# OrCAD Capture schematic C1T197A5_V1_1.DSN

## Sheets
1 002_Block digram: title: Telink-Semi; rev: V1.1; note: C1T197A5
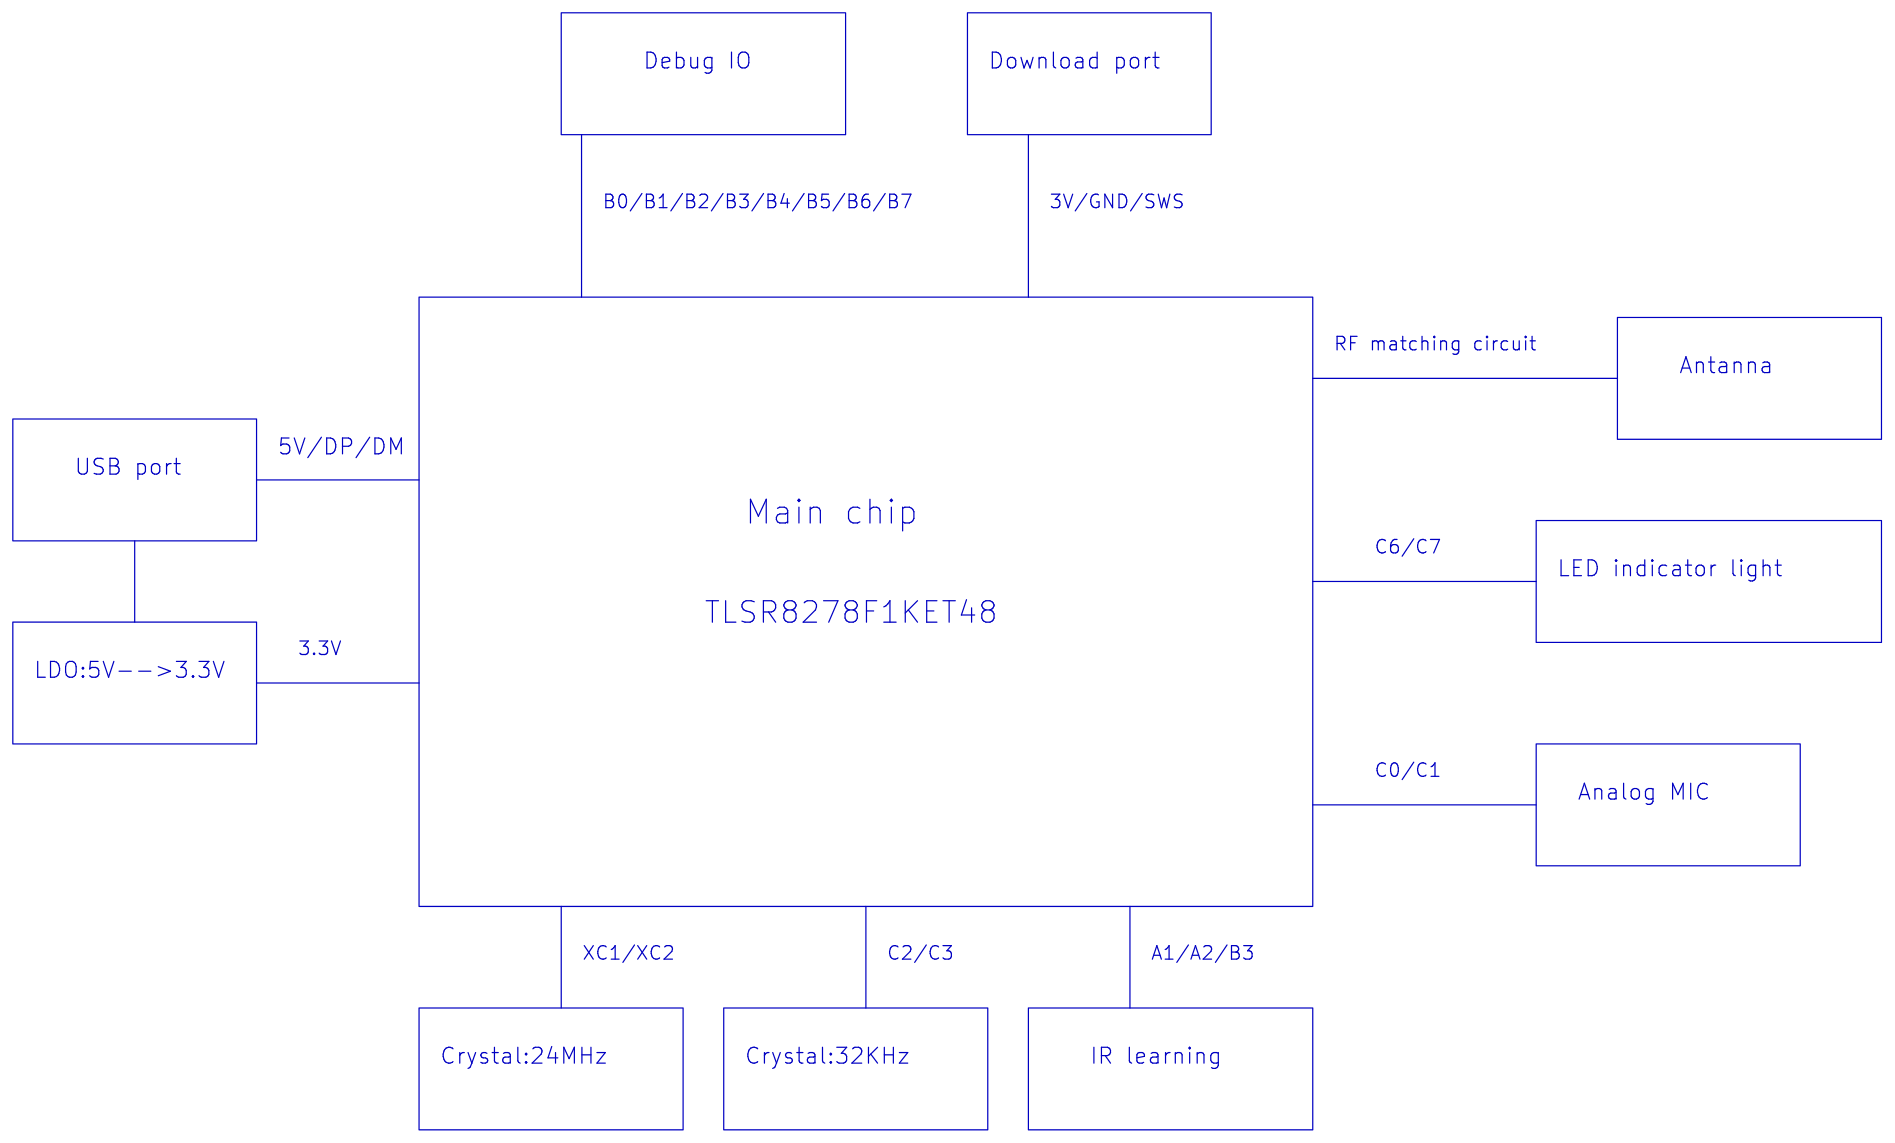
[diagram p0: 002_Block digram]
2 001_Log
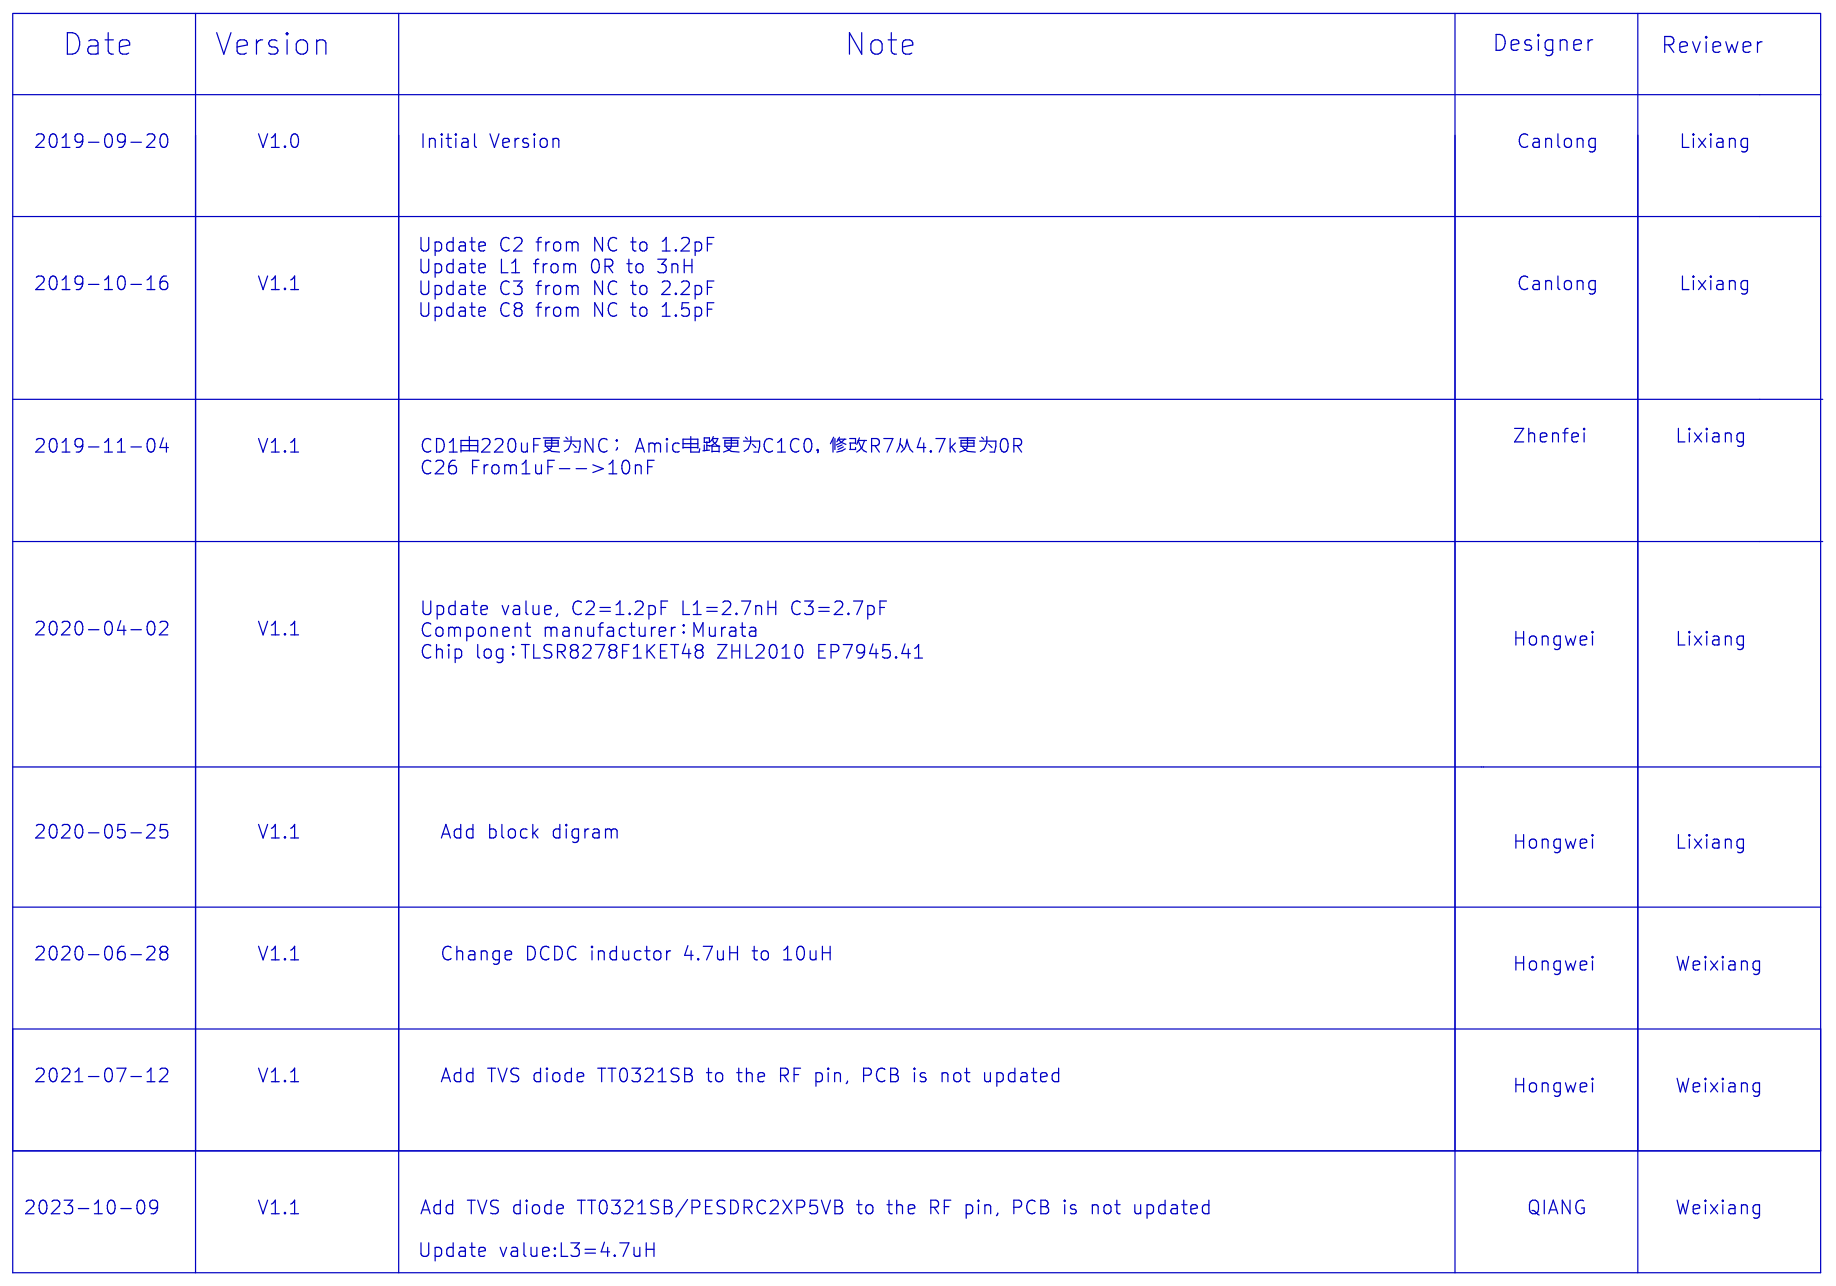
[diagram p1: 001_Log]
3 003_CPU: size A4
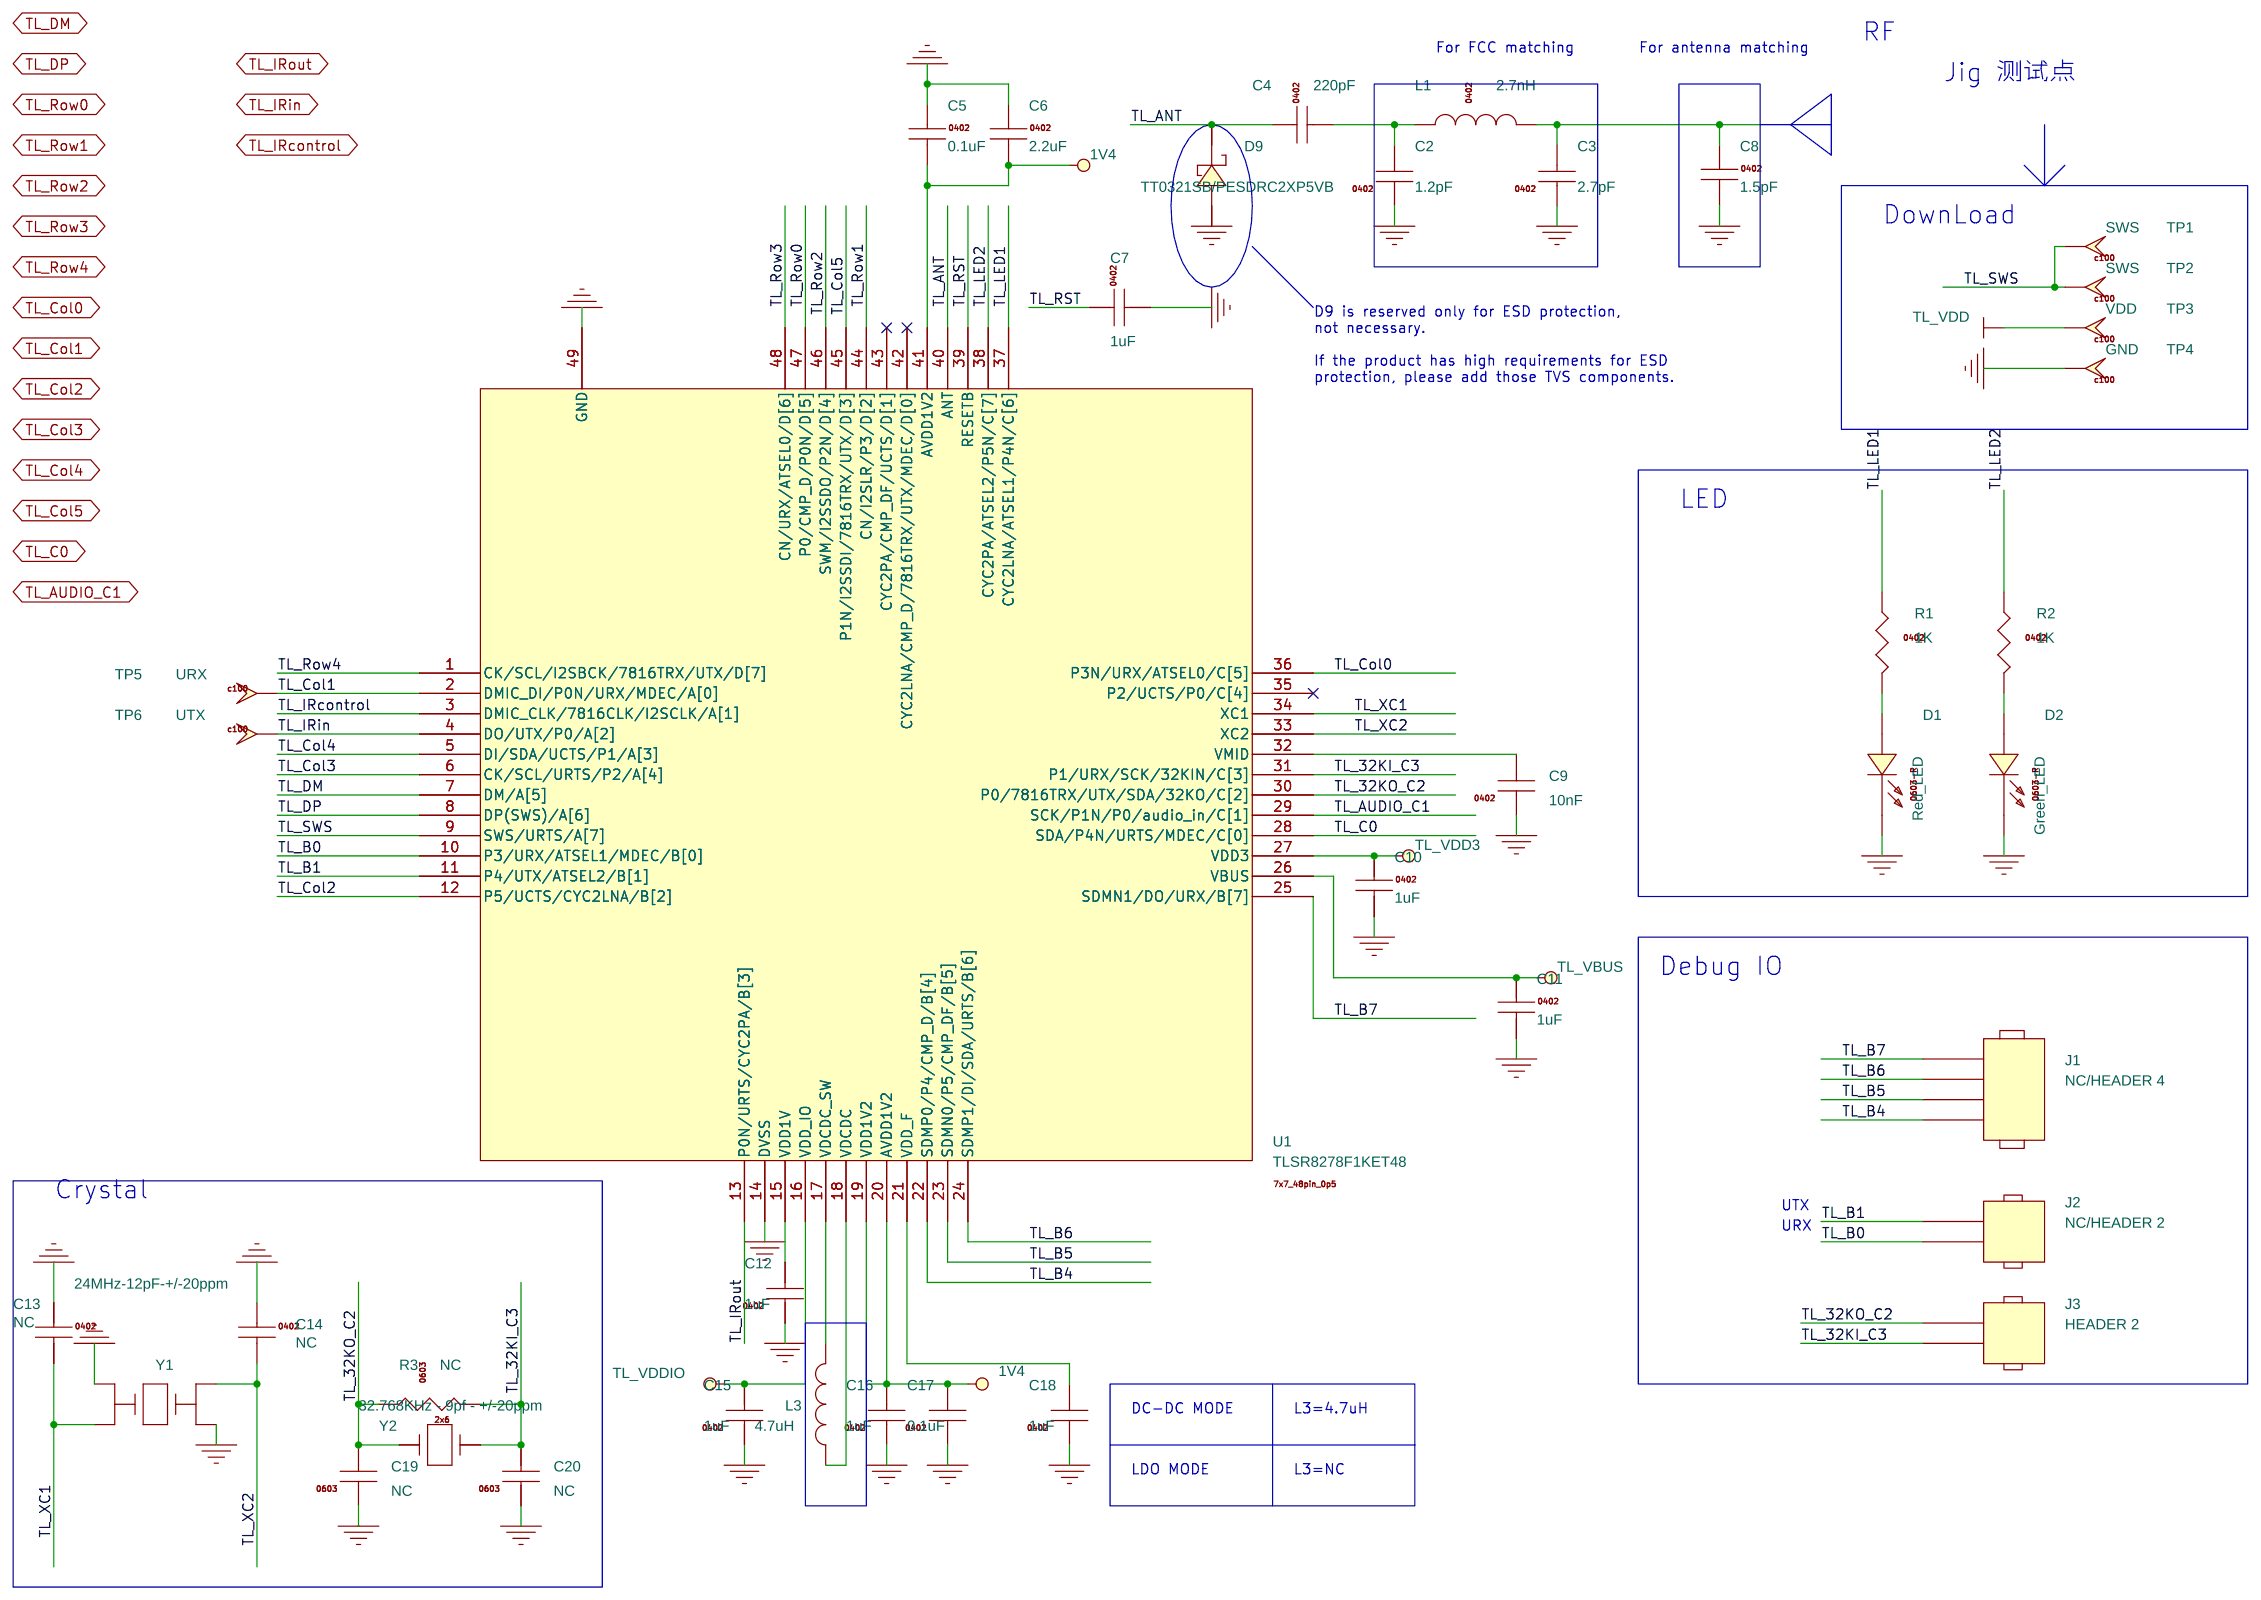
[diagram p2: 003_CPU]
4 004_Key: size A4
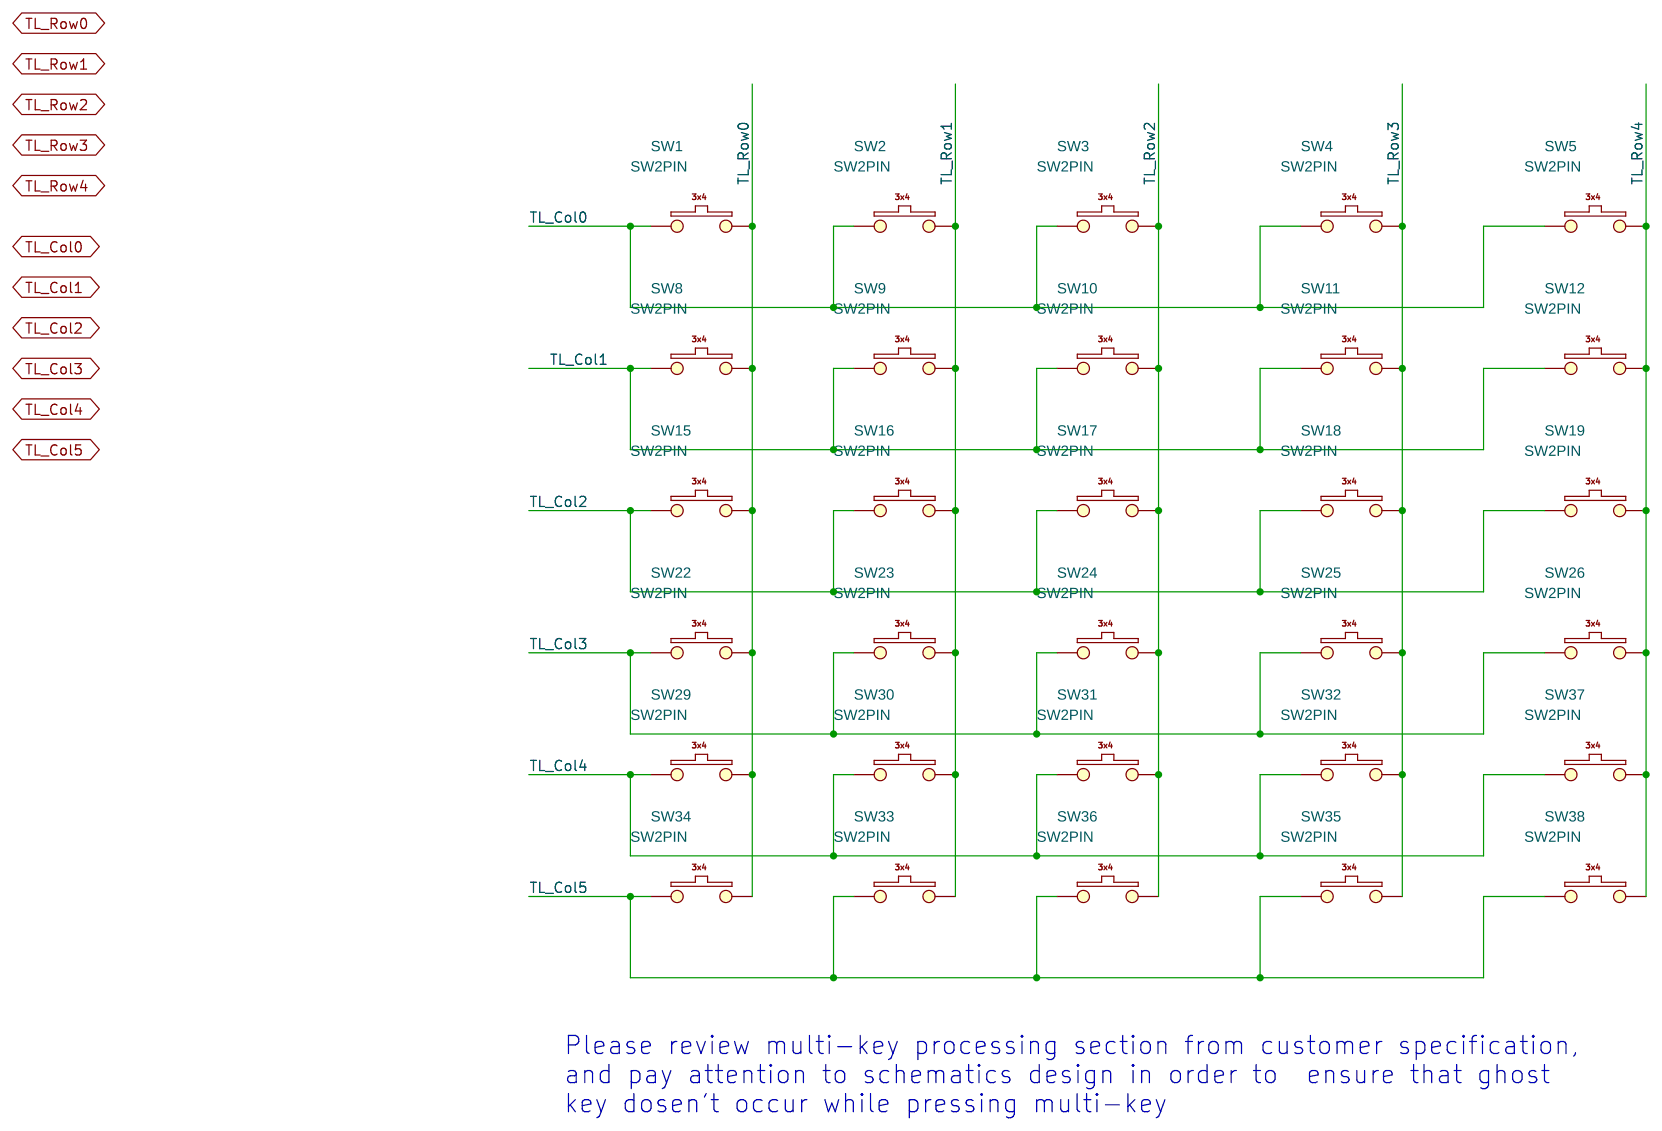
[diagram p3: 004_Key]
5 005_Power: size A4
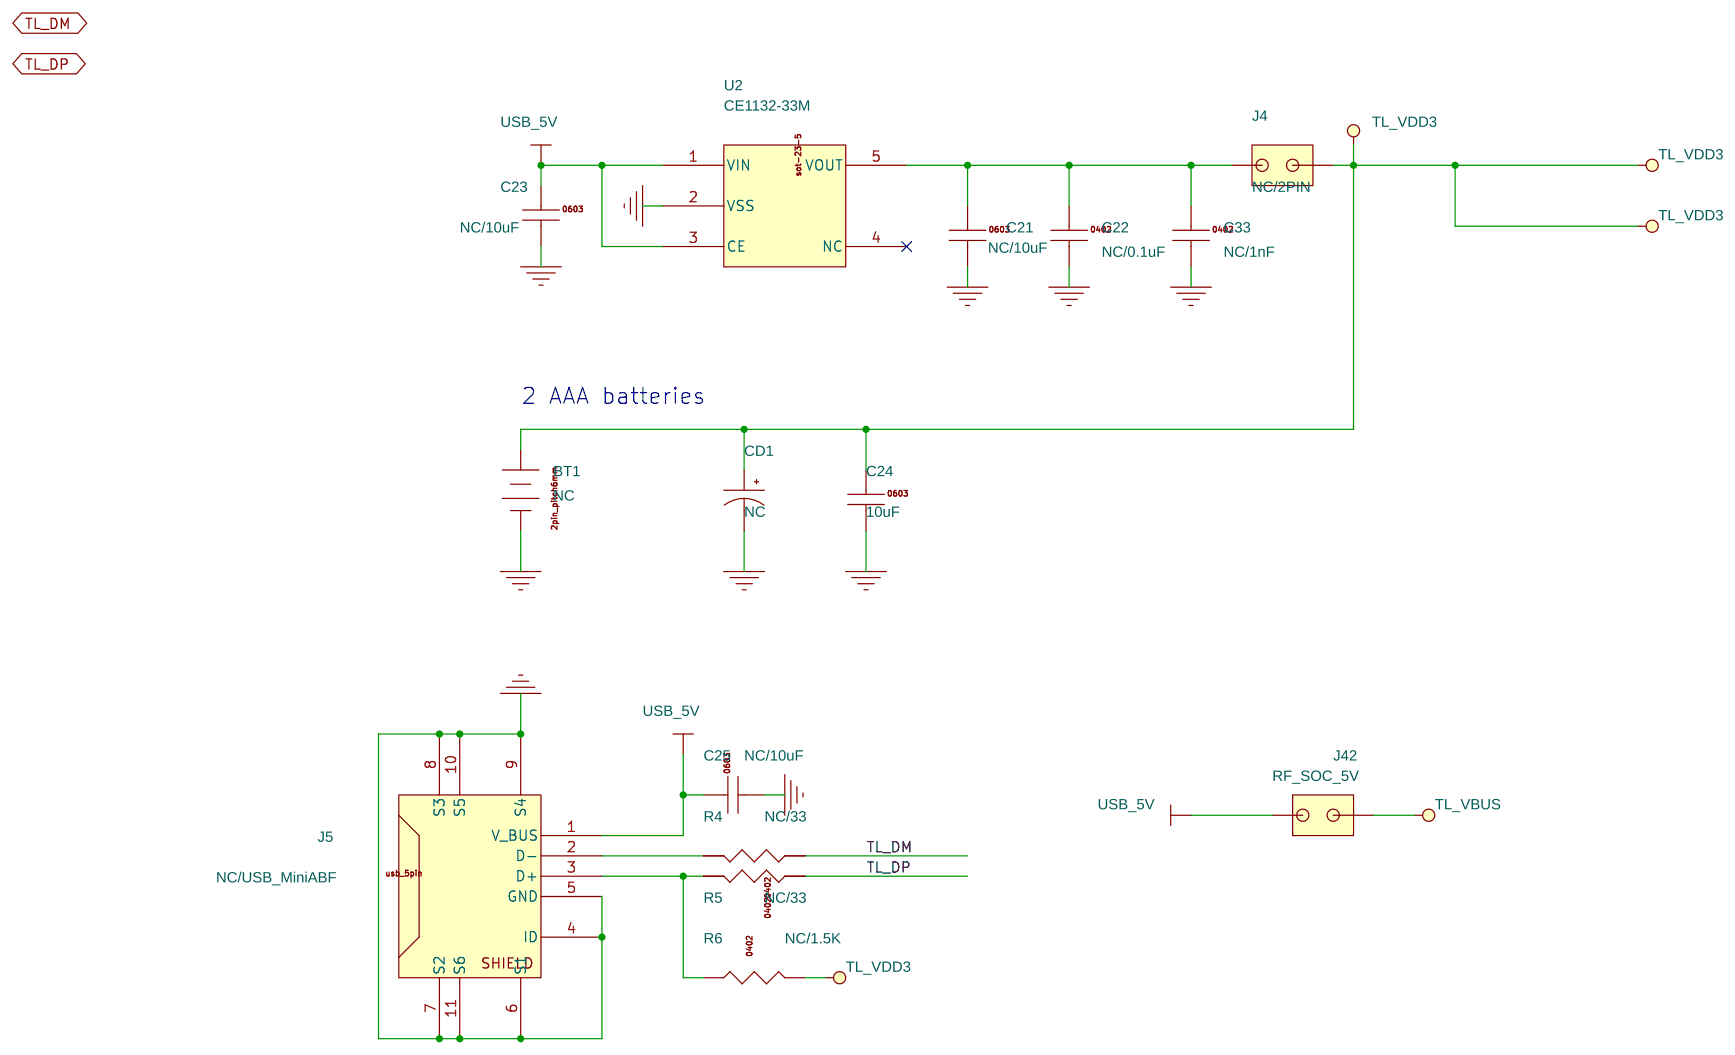
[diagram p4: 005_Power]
6 006_Audio: size A4
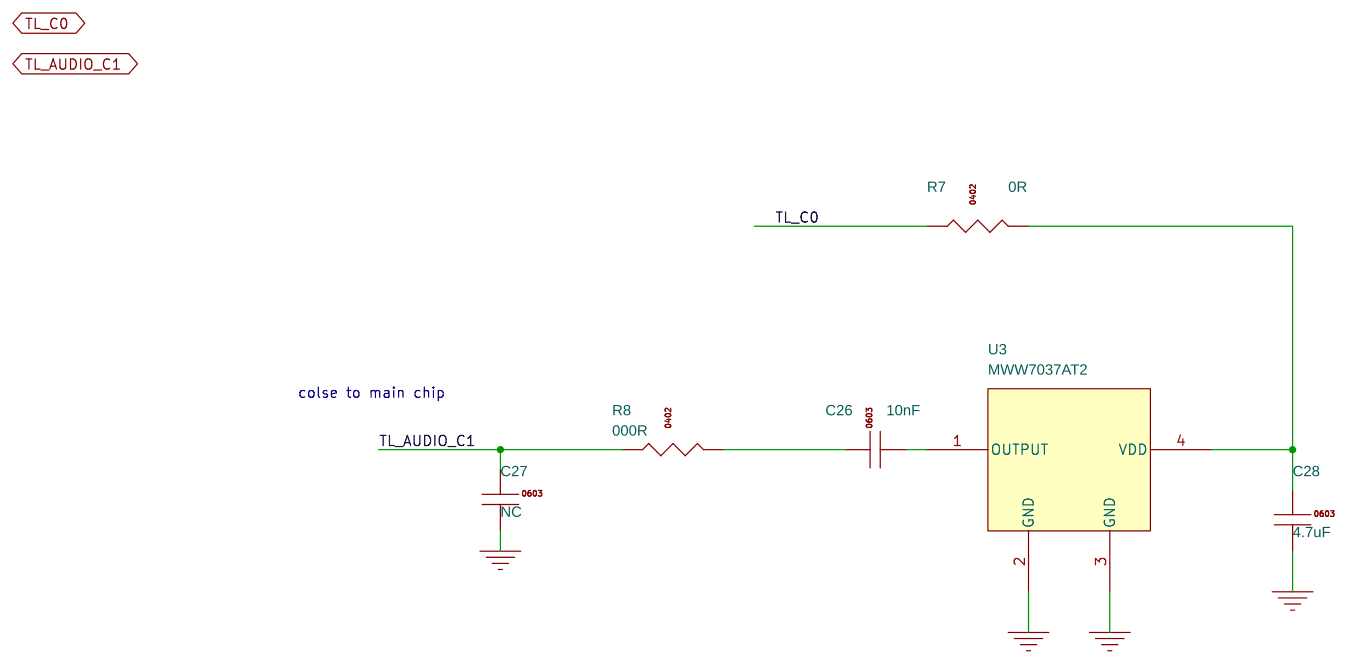
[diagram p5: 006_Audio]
7 007_IR: size A4
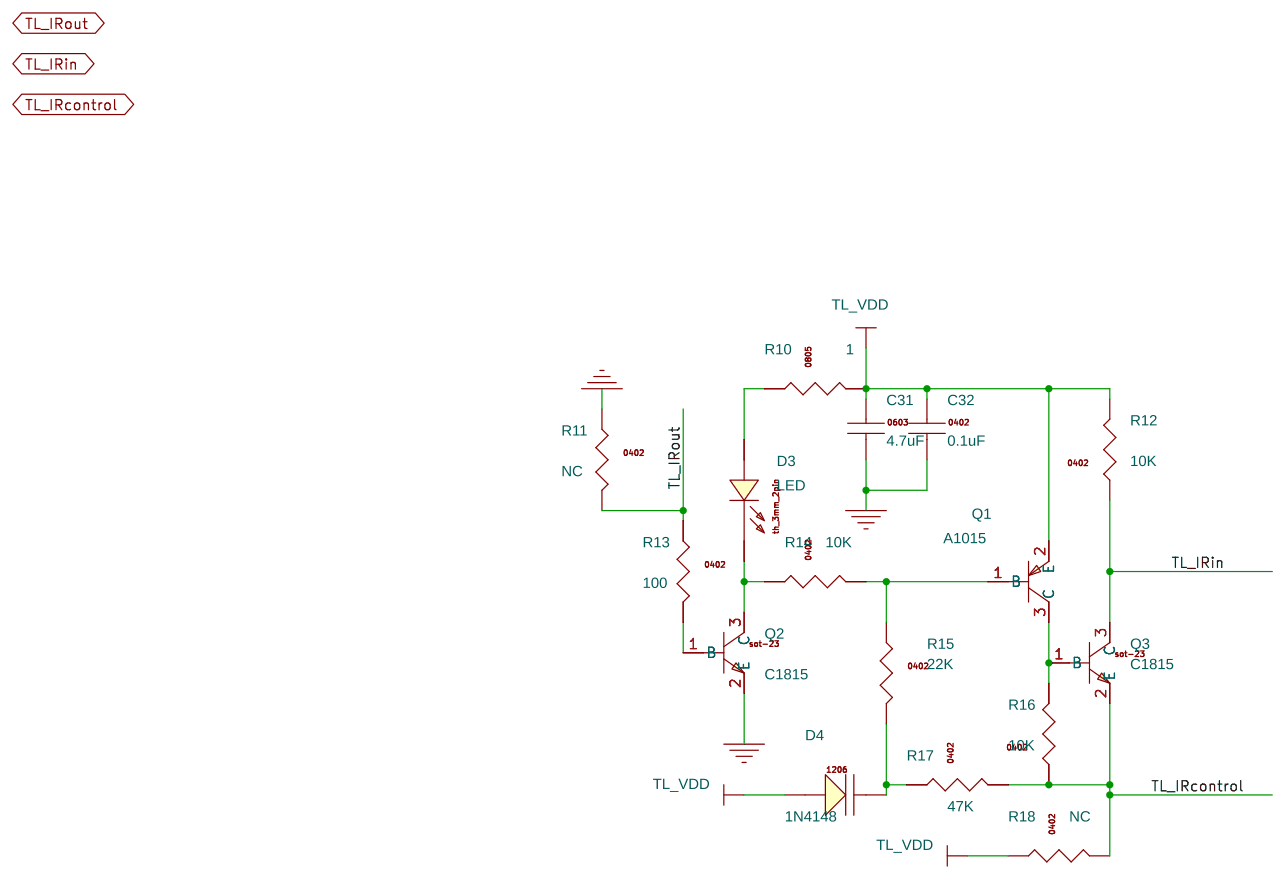
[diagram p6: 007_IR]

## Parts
sheet 003_CPU
C2  1.2pF  [0402]
C3  2.7pF  [0402]
C4  220pF  [0402]
C5  0.1uF  [0402]
C6  2.2uF  [0402]
C7  1uF  [0402]
C8  1.5pF  [0402]
C9  10nF  [0402]
C10  1uF  [0402]
C11  1uF  [0402]
C12  1uF  [0402]
C13  NC  [0402]
C14  NC  [0402]
C15  1uF  [0402]
C16  1uF  [0402]
C17  0.1uF  [0402]
C18  1uF  [0402]
C19  NC  [0402]
C20  NC  [0402]
D1  Red_LED  [0603-LED]
D2  Green_LED  [0603-LED]
D9  TT0321SB/PESDRC2XP5VB  [SOD-123]
J1  NC/HEADER 4  [hdr254f-1x4x850]
J2  NC/HEADER 2  [hdr254f-1x2x850]
J3  HEADER 2  [hdr254f-1x2x850]
L1  2.7nH  [0402]
L3  4.7uH  [0805L]
R1  1K  [0402]
R2  1K  [0402]
R3  NC  [0402]
TP1  SWS  [tp100]
TP2  SWS  [tp100]
TP3  VDD  [tp100]
TP4  GND  [tp100]
TP5  URX  [tp100]
TP6  UTX  [tp100]
U1  TLSR8278F1KET48  [qfn_7x7_48pin_0p5_4p20x4p20]
Y1  24MHz-12pF-+/-20ppm  [OSCCC250X320X110]
Y2  32.768KHz - 9pf - +/-20ppm  [OSC_2x6]
sheet 004_Key
SW1  SW2PIN  [sw_out6_in3]
SW2  SW2PIN  [sw_out6_in3]
SW3  SW2PIN  [sw_out6_in3]
SW4  SW2PIN  [sw_out6_in3]
SW5  SW2PIN  [sw_out6_in3]
SW8  SW2PIN  [sw_out6_in3]
SW9  SW2PIN  [sw_out6_in3]
SW10  SW2PIN  [sw_out6_in3]
SW11  SW2PIN  [sw_out6_in3]
SW12  SW2PIN  [sw_out6_in3]
SW15  SW2PIN  [sw_out6_in3]
SW16  SW2PIN  [sw_out6_in3]
SW17  SW2PIN  [sw_out6_in3]
SW18  SW2PIN  [sw_out6_in3]
SW19  SW2PIN  [sw_out6_in3]
SW22  SW2PIN  [sw_out6_in3]
SW23  SW2PIN  [sw_out6_in3]
SW24  SW2PIN  [sw_out6_in3]
SW25  SW2PIN  [sw_out6_in3]
SW26  SW2PIN  [sw_out6_in3]
SW29  SW2PIN  [sw_out6_in3]
SW30  SW2PIN  [sw_out6_in3]
SW31  SW2PIN  [sw_out6_in3]
SW32  SW2PIN  [sw_out6_in3]
SW33  SW2PIN  [sw_out6_in3]
SW34  SW2PIN  [sw_out6_in3]
SW35  SW2PIN  [sw_out6_in3]
SW36  SW2PIN  [sw_out6_in3]
SW37  SW2PIN  [sw_out6_in3]
SW38  SW2PIN  [sw_out6_in3]
sheet 005_Power
BT1  NC  [bat_2dip]
C21  NC/10uF  [0603c]
C22  NC/0.1uF  [0402]
C23  NC/10uF  [0603c]
C24  10uF  [0603c]
C25  NC/10uF  [0603c]
C33  NC/1nF  [0402]
CD1  NC  [cd2p0_4p0b]
J4  NC/2PIN  [HDR254F-1X2X850]
J5  NC/USB_MiniABF  [microusb_dip]
J42  RF_SOC_5V  [HDR254F-1X2X850]
R4  NC/33  [0402]
R5  NC/33  [0402]
R6  NC/1.5K  [0402]
U2  CE1132-33M  [sot-23-5]
sheet 006_Audio
C26  10nF  [0402]
C27  NC  [0402]
C28  4.7uF  [0402]
R7  0R  [0402]
R8  000R  [0402]
U3  MWW7037AT2  [ga_bfa423_a83]
sheet 007_IR
C31  4.7uF  [0402]
C32  0.1uF  [0402]
D3  LED  [led_th_2p54mm_2pin]
D4  1N4148  [SOD80]
Q1  A1015  [SOT-23]
Q2  C1815  [SOT-23]
Q3  C1815  [SOT-23]
R10  1  [0402]
R11  NC  [0402]
R12  10K  [0402]
R13  100  [0402]
R14  10K  [0402]
R15  22K  [0402]
R16  10K  [0402]
R17  47K  [0402]
R18  NC  [0402]

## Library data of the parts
C2-C4 C8 = C1608_NC_0
C5-C7 C9-C11 C22 C32 C33 = C1005X5R1C104K
C12 C15-C18 = C1005X5R1C105K
C13 C14 = C1005_NC
C19 C20 = C1608_NC
D1 D2 = 0603D_Red
D9 = DIODE_SCHOTTKY_0
J1 = HEADER_4
J2 J3 = HEADER_2
L1 = MLK1608_0
L3 = IND_0
R1 R2 R6-R8 = RS0402K472JT
R3 = RS0603K102JT
TP1-TP6 = TestPad100
U1 = TLSR8278F1KET48_2
Y1 = CRYSTAL4_SM_0
Y2 = OSC_2x6_2pin_16Mhz
SW1-SW5 SW8-SW12 SW15-SW19 SW22-SW26 SW29-SW38 = SW2PIN_0
BT1 = BATTERY_2xAAA_3V
C21 C23 C25 = C1608X5R1A106K
C24 = C1608X5R0J106M
CD1 = CD_220uF_16V
J4 = B2S_2: PAGE: POWER
J5 = USB_MiniABF_2
J42 = B2S_3: PAGE: POWER
R4 R5 = RS0402K330JT
U2 = XC6219_6.3V_SOT-23-5
C26-C28 = C1608X5R0J475M
U3 = MULPS4CX-RM5_0
C31 = C1608X5R1A226M
D3 = Led_Th_3mm_1
D4 = Diode_1N4148
Q1 = PNP_A1015
Q2 Q3 = NPN_C1815
R10 = RS0805K1R0JT
R11 R18 = RS0402_NC
R12 R14 R16 = RS0402K103JT
R13 = RS0402K101JT
R15 = RS0402K223JT
R17 = RS0402K473JT

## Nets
1V4: C5.2 C6.2 C16.2 C17.2 U1.19(VDD1V2) U1.20(AVDD1V2) U1.41(AVDD1V2)
GND: BT1.2(-) C2.1 C3.1 C5.1 C6.1 C7.2 C8.2 C9.1 C10.2 C11.2 C12.1 C13.1 C14.1 C15.1 C16.1 C17.1 C18.1 C19.1 C20.1 C21.2 C22.2 C23.2 C24.2 C25.2 C27.2 C28.2 C31.2 C32.2 C33.2 CD1.2 D1.C(CATHODE) D2.C(CATHODE) D9.A(ANODE) J5.4(ID) J5.5(GND) J5.6(S1) J5.7(S2) J5.8(S3) J5.9(S4) J5.10(S5) J5.11(S6) Q2.2(E) R11.1 TP4.1(TP) U1.14(DVSS) U1.49(GND) U2.2(VSS) U3.2(GND) U3.3(GND) Y1.2 Y1.4
TL_32KI_C3: C20.2 J3.2 R3.2 U1.31(P1/URX/SCK/32KIN/C[3]) Y2.2
TL_32KO_C2: C19.2 J3.1 R3.1 U1.30(P0/7816TRX/UTX/SDA/32KO/C[2]) Y2.1
TL_ANT: C4.1 D9.C(CATHODE) U1.40(ANT)
TL_AUDIO_C1: U1.29(SCK/P1N/P0/audio_in/C[1])
TL_AUDIO_C1 (page 006_Audio): C27.1 R8.1
TL_B0: J2.2 U1.10(P3/URX/ATSEL1/MDEC/B[0])
TL_B1: J2.1 U1.11(P4/UTX/ATSEL2/B[1])
TL_B4: J1.1 U1.22(SDMP0/P4/CMP_D/B[4])
TL_B5: J1.2 U1.23(SDMN0/P5/CMP_DF/B[5])
TL_B6: J1.3 U1.24(SDMP1/DI/SDA/URTS/B[6])
TL_B7: J1.4 U1.25(SDMN1/DO/URX/B[7])
TL_C0: U1.28(SDA/P4N/URTS/MDEC/C[0])
TL_C0 (page 006_Audio): R7.1
TL_Col0: U1.36(P3N/URX/ATSEL0/C[5])
TL_Col0 (page 004_Key): SW1.1 SW2.1 SW3.1 SW4.1 SW5.1
TL_Col1: TP5.1(TP) U1.2(DMIC_DI/P0N/URX/MDEC/A[0])
TL_Col1 (page 004_Key): SW8.1 SW9.1 SW10.1 SW11.1 SW12.1
TL_Col2: U1.12(P5/UCTS/CYC2LNA/B[2])
TL_Col2 (page 004_Key): SW15.1 SW16.1 SW17.1 SW18.1 SW19.1
TL_Col3: U1.6(CK/SCL/URTS/P2/A[4])
TL_Col3 (page 004_Key): SW22.1 SW23.1 SW24.1 SW25.1 SW26.1
TL_Col4: U1.5(DI/SDA/UCTS/P1/A[3])
TL_Col4 (page 004_Key): SW29.1 SW30.1 SW31.1 SW32.1 SW37.1
TL_Col5: U1.45(P1N/I2SSDI/7816TRX/UTX/D[3])
TL_Col5 (page 004_Key): SW33.1 SW34.1 SW35.1 SW36.1 SW38.1
TL_DM: U1.7(DM/A[5])
TL_DM (page 005_Power): R4.1
TL_DP: U1.8(DP(SWS)/A[6])
TL_DP (page 005_Power): R5.1
TL_IRcontrol: U1.3(DMIC_CLK/7816CLK/I2SCLK/A[1])
TL_IRcontrol (page 007_IR): Q3.2(E) R16.1 R17.2 R18.2
TL_IRin: TP6.1(TP) U1.4(DO/UTX/P0/A[2])
TL_IRin (page 007_IR): Q3.3(C) R12.1
TL_IRout: U1.13(P0N/URTS/CYC2PA/B[3])
TL_IRout (page 007_IR): R11.2 R13.1
TL_LED1: R1.1 U1.37(CYC2LNA/ATSEL1/P4N/C[6])
TL_LED2: R2.1 U1.38(CYC2PA/ATSEL2/P5N/C[7])
TL_Row0: U1.47(P0/CMP_D/P0N/D[5])
TL_Row0 (page 004_Key): SW1.2 SW8.2 SW15.2 SW22.2 SW29.2 SW34.2
TL_Row1: U1.44(CN/I2SLR/P3/D[2])
TL_Row1 (page 004_Key): SW2.2 SW9.2 SW16.2 SW23.2 SW30.2 SW33.2
TL_Row2: U1.46(SWM/I2SSDO/P2N/D[4])
TL_Row2 (page 004_Key): SW3.2 SW10.2 SW17.2 SW24.2 SW31.2 SW36.2
TL_Row3: U1.48(CN/URX/ATSEL0/D[6])
TL_Row3 (page 004_Key): SW4.2 SW11.2 SW18.2 SW25.2 SW32.2 SW35.2
TL_Row4: U1.1(CK/SCL/I2SBCK/7816TRX/UTX/D[7])
TL_Row4 (page 004_Key): SW5.2 SW12.2 SW19.2 SW26.2 SW37.2 SW38.2
TL_RST: C7.1 U1.39(RESETB)
TL_SWS: TP1.1(TP) TP2.1(TP) U1.9(SWS/URTS/A[7])
TL_VBUS: C11.1 J42.2 U1.26(VBUS)
TL_VDD: BT1.1(+) C10.1 C15.2 C24.1 C31.1 C32.1 CD1.1 D4.A J4.2 Q1.2(E) R6.2 R10.2 R12.2 R18.1 TP3.1(TP) U1.16(VDD_IO) U1.27(VDD3)
TL_XC1: C13.2 U1.34(XC1) Y1.3
TL_XC2: C14.2 U1.33(XC2) Y1.1
USB_5V: C23.1 C25.1 J5.1(V_BUS) J42.1 U2.1(VIN) U2.3(CE)
N21000893: D2.A(ANODE) R2.2
N21007782: D1.A(ANODE) R1.2
N21081547: C21.1 C22.1 C33.1 J4.1 U2.5(VOUT)
N21108187: D3.A(ANODE) R10.1
N21108227: D4.C R15.2 R17.1
N21108333: Q2.1(B) R13.2
N21108349: D3.C(CATHODE) Q2.3(C) R14.1
N21108369: Q1.3(C) Q3.1(B) R16.2
N21108379: Q1.1(B) R14.2 R15.1
N21115397: C3.2 C8.1 L1.2
N21115407: C2.2 C4.2 L1.1
N21116055: C12.2 U1.15(VDD1V)
N21116211: L3.2 U1.17(VDCDC_SW)
N21116214: L3.1 U1.18(VDCDC)
N21116508: C18.2 U1.21(VDD_F)
N21117063: C9.2 U1.32(VMID)
N21119406: J5.3(D+) R5.2 R6.1
N21119472: J5.2(D-) R4.2
N21128727: C28.1 R7.2 U3.4(VDD)
N21128765: C26.1 R8.2
N21128767: C26.2 U3.1(OUTPUT)

Not connected (* = marked no-connect by the designer): U1 35(P2/UCTS/P0/C[4])* 42(CYC2LNA/CMP_D/7816TRX/UTX/MDEC/D[0])* 43(CYC2PA/CMP_DF/UCTS/D[1])*; U2 4(NC)*

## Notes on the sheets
sheet 1
- Debug IO
- Download port
- B0/B1/B2/B3/B4/B5/B6/B7
- 3V/GND/SWS
- RF matching circuit
- Antanna
- 5V/DP/DM
- USB port
- Main chip
- C6/C7
- LED indicator light
- TLSR8278F1KET48
- 3.3V
- LDO:5V-->3.3V
- C0/C1
- Analog MIC
- XC1/XC2
- C2/C3
- A1/A2/B3
- Crystal:24MHz
- Crystal:32KHz
- IR learning
sheet 2
- Date
- Version
- Note
- Designer
- Reviewer
- 2019-09-20
- V1.0
- Initial Version
- Canlong
- Lixiang
- Update C2 from NC to 1.2pF
  Update L1 from 0R to 3nH
  Update C3 from NC to 2.2pF
  Update C8 from NC to 1.5pF
- 2019-10-16
- V1.1
- Canlong
- Lixiang
- Zhenfei
- Lixiang
- 2019-11-04
- V1.1
- CD1由220uF更为NC； Amic电路更为C1C0，修改R7从4.7k更为0R
  C26 From1uF-->10nF
- Update value, C2=1.2pF L1=2.7nH C3=2.7pF
  Component manufacturer：Murata
  Chip log：TLSR8278F1KET48 ZHL2010 EP7945.41
- 2020-04-02
- V1.1
- Hongwei
- Lixiang
- 2020-05-25
- V1.1
- Add block digram
- Hongwei
- Lixiang
- 2020-06-28
- V1.1
- Change DCDC inductor 4.7uH to 10uH
- Hongwei
- Weixiang
- 2021-07-12
- V1.1
- Add TVS diode TT0321SB to the RF pin, PCB is not updated
- Hongwei
- Weixiang
- 2023-10-09
- V1.1
- Add TVS diode TT0321SB/PESDRC2XP5VB to the RF pin, PCB is not updated
- QIANG
- Weixiang
- Update value:L3=4.7uH
sheet 3
- RF
- For FCC matching
- For antenna matching
- Jig 测试点
- DownLoad
- D9 is reserved only for ESD protection,
  not necessary.
  If the product has high requirements for ESD
  protection, please add those TVS components.
- LED
- Debug IO
- Crystal
- UTX
- URX
- DC-DC MODE
- L3=4.7uH
- LDO MODE
- L3=NC
sheet 4
- Please review multi-key processing section from customer specification,
  and pay attention to schematics design in order to  ensure that ghost
  key dosen't occur while pressing multi-key
sheet 5
- 2 AAA batteries
sheet 6
- colse to main chip
